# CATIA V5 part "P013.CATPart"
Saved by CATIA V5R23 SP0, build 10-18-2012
Part number: P013
Definition: Flasque avant
Bounding box of the stored display mesh (mm): x 28 to 53, y -57.5 to 57.5, z -57.5 to 57.5
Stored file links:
  C:\wamp\www\COURS\CONCEPTION GMP1\TITRE 02-SEMESTRE 2\03-TP7-PRESSE MECANIQUE\eleve\P013.CATPart
  C:\Documents and Settings\Samuel\Mes documents\Cours\Projet Tutoret\Licence Pro - Presse\Presse\Presse mecanique.CATProduct
  C:\Documents and Settings\Samuel\Mes documents\Cours\Projet Tutoret\Licence Pro - Presse\Presse\Bati gauche.CATPart
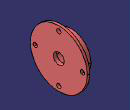
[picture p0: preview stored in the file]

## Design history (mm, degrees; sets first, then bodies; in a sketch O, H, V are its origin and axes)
Body1 (main body)
  Sketch1 on yz-plane, origin (0, 0, 0), H (0, 1, 0), V (0, 0, 1)
    circle A1 centre (0, 0) radius 40
    radius A1 = 40
  Pad1: profile Sketch1, direction (1, 0, 0), length 48, opposite side length -28
  Sketch2 on face of Pad1, origin (48, 0, 0), H (0, 1, 0), V (0, 0, 1)
    circle A1 centre (0, 0) radius 57.5
    radius A1 = 57.5
  Pad2: profile Sketch2, direction (1, 0, 0), length 5
  Sketch3 on face of Pad2, origin (53, 0, 0), H (0, 1, 0), V (0, 0, 1)
    point P1 (0, 0)
    reference projected circle E1 centre (0, 0) radius 57.5 from edge [face of Pad2 | face of Pad2]
    concentricity: P1 E1
  Hole1: placed by Sketch3, at (53, 0, 0) direction (-1, 0, 0), diameter 22, through (limit type 3)
  Sketch4 on face of Pad1, origin (28, 0, 0), H (0, 1, 0), V (0, 0, -1)
    point P1 (0, 0)
  Hole2: placed by Sketch4, at (28, 0, 0) direction (1, 0, 0), diameter 47, depth 12
  Sketch5 on face of Pad2, origin (53, 0, 0), H (0, 1, 0), V (0, 0, 1)
    point P1 (0, 48)
    distance H P1 = 48
    coincidence: P1 V
  Hole3: placed by Sketch5, at (53, 0, 48) direction (-1, 0, 0), diameter 8.5, through (limit type 6)
  CircPattern1: of Hole3, instances 4, angular step 90, axis from face of Pad2
  Sketch6 on face of Hole2, origin (40, 13.0309, -7.1716), H (0, 1, 0), V (0, 0, -1)
    point P1 (-13.0309, -7.1716)
    reference projected circle E1 centre (-13.0309, -7.1716) radius 11 from edge [face of Hole1 | face of Hole2]
    concentricity: E1 P1
  Hole4: placed by Sketch6, at (40, 0, 0) direction (1, 0, 0), diameter 45, depth 6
